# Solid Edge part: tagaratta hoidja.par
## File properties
Title: tagaratta hoidja
Author: Stella-Marii
Template: Iso Metric Part.par
Last saved by: Stella-Marii
Revision: 13
Application: Solid Edge
Density: 7833,000 kg/m^3
Accuracy: 0,990
Username: Stella-Marii
Document Number: 38
Material: Steel, structural
Face Style: Steel
Fill Style: ANSI32(Steel)
Virtual Style: Brushed steel
Grouping: Metals\Steel
LibraryName: Materials
Coef. of Thermal Exp: 1.3e-05
Thermal Conductivity: 32.0
Specific Heat: 481.0
Modulus of Elasticity: 199947953000.0
Poisson's Ratio: 0.29
Yield Stress: 262000766.0
Ultimate Stress: 358527364.0
Elongation: 0.0
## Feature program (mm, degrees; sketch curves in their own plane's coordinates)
sketch for "unnamed Protrusion 1" plane through (0, 0, 0) normal (1, 0, 0) x-axis (0, 1, 0)
  line (-10, -15) -> (10, -15)
  line (10, -15) -> (10, 15)
  line (10, 15) -> (-10, 15)
  line (-10, 15) -> (-10, -15)
  dimension (linear) = 10
  dimension (linear) = 10
extrude "unnamed Protrusion 1" add finite 150 symmetric
draft "Draft_2"  Angles1 = 15 deg
sketch for "ExtrudedProtrusion_2" plane through (-6.6987, 10, 0) normal (0, 1, 0) x-axis (1, 0, 0)
extrude "ExtrudedProtrusion_2" add finite 5 along +normal
replace surface "unnamed ReplaceSurface 1"
fillet "Round_1" radius 20
fillet "Round_2" radius 20
chamfer "Chamfer_1" setback 20
fillet "Round_3" radius 10
sketch for "Hole_1" plane through (0, 0, 0) normal (0, -1, 0) x-axis (1, 0, 0)
  hole centre (55, 0) bore radius 4.188
hole "Hole_1" nominal diameter 10 finite
Other named dimensions: "ExtrudedSurface_1": FiniteDepth = 135.8225 mm
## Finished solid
Body 1: sheet body, 1 face, 4 edges, 4 vertices.
  Faces by surface: swept 1
  Edges by curve: line 2, spline 2
Body 2: solid body, 14 faces, 32 edges, 20 vertices.
  Faces by surface: plane 8, cylinder 3, blend 2, swept 1
  Edges by curve: line 16, intersection 11, ellipse 4, circle 1
Bounding box of the edges (mm; curved faces can reach further): 184.052 x 40.976 x 136.021, from (-83.0385, -10, -68.0057) to (101.0138, 30.9761, 68.0157).
Cylindrical faces by radius (mm): R4.188 x1, R10 x2
Planar faces by outward normal: +x 1, +y 2, +z 1, -y 1, -z 1, oblique 2
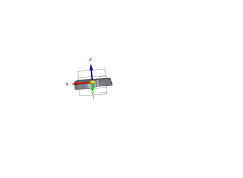
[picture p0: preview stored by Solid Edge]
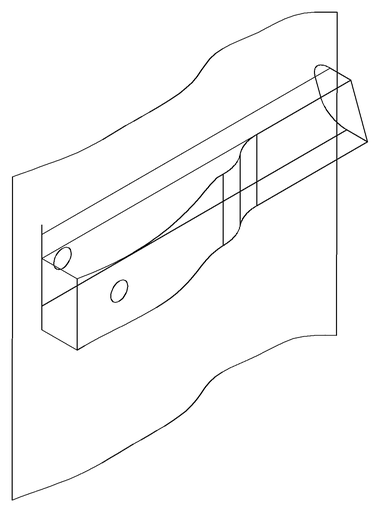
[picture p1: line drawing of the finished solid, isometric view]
